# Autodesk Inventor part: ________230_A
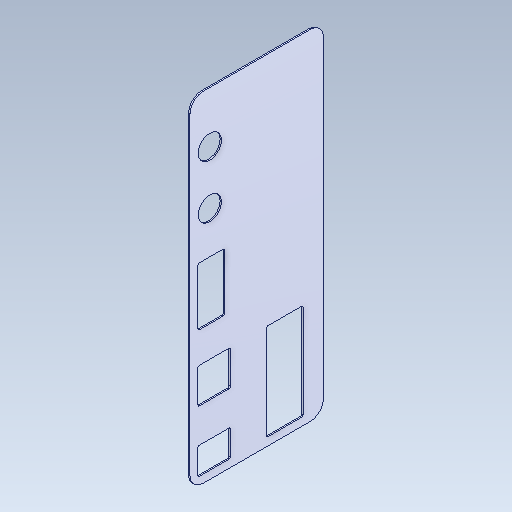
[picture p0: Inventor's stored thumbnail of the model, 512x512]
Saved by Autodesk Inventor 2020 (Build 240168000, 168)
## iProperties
Created: 2017-09
Part Number: ________230_A
Material: Générique
Document SubType Name: Modeling
Designer: bruno
Density: 1 g/cm^3
Appearance: Par défaut
Author: bruno
Sending System: SolidWorks 2016
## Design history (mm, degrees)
feature "Importée1"
node "Solide1"
